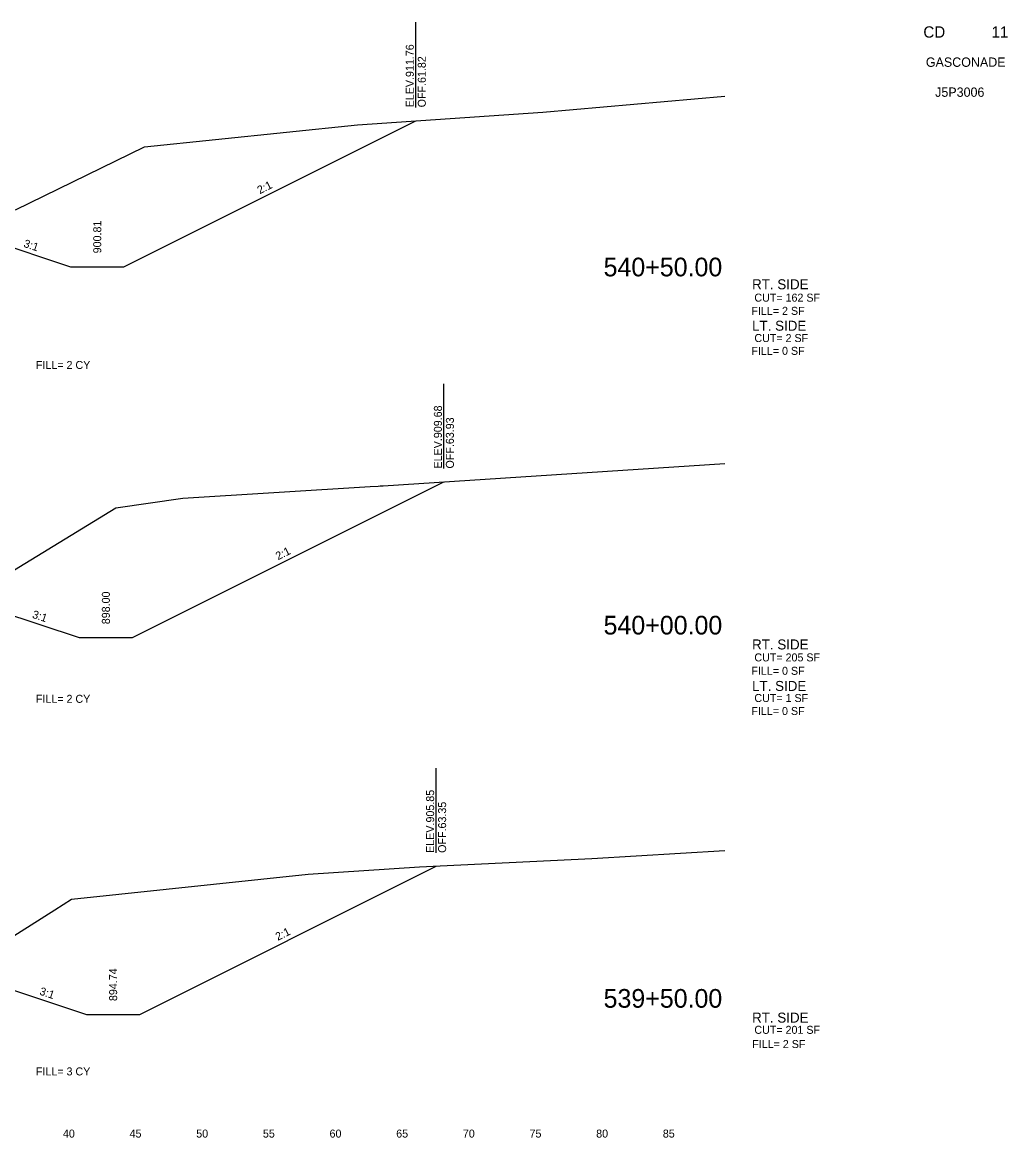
# Model space of a CAD drawing. Extents: x -4 to 359, y 0 to 1436.
# Drawn here: x 284.8 to 358.7, y 0.5 to 84.1 of the extents above; entities that cross this region are included whole.
import ezdxf

# ---------------------------------------------------------------- set-up
doc = ezdxf.new("R2010")
doc.units = 0
for name, color, linetype in [('Common-Title block info', 7, 'Continuous'), ('XS-Existing surface-ground', 7, 'Continuous'), ('XS-Proposed surface-ground', 7, 'Continuous'), ('XS-Text-ditch slope', 7, 'Continuous'), ('XS-Text-earthwork labels', 7, 'Continuous'), ('XS-Text-offset label', 7, 'Continuous'), ('XS-Text-profile report', 7, 'Continuous'), ('XS-Text-tie elevation', 7, 'Continuous'), ('XS-Text-tie offset', 7, 'Continuous')]:
    doc.layers.add(name, color=color, linetype=linetype)

msp = doc.modelspace()

# ---------------------------------------------------------------- linework, layer by layer
at = {"layer": 'XS-Existing surface-ground'}
for p, q in [((323.848, 77.412), (337.5, 78.606)), ((309.95, 76.461), (323.848, 77.412)), ((293.97, 74.809), (309.95, 76.461)), ((284.298, 70.082), (293.97, 74.809)), ((311.878, 49.381), (337.5, 51.043)), ((310.895, 49.334), (311.501, 49.361)), ((311.501, 49.361), (311.661, 49.369)), ((311.661, 49.369), (311.878, 49.381)), ((296.854, 48.45), (310.895, 49.334)), ((283.766, 42.803), (291.825, 47.733)), ((291.825, 47.733), (296.854, 48.45)), ((327.52, 21.421), (337.5, 22.029)), ((314.61, 20.792), (327.52, 21.421)), ((288.503, 18.369), (306.248, 20.266)), ((306.248, 20.266), (314.61, 20.792)), ((275.635, 10.244), (287.236, 17.592)), ((287.236, 17.592), (288.503, 18.369))]:
    msp.add_line(p, q, dxfattribs=at)
at = {"layer": 'XS-Proposed surface-ground'}
for points in [[(282.427, 67.793), (288.427, 65.813), (292.427, 65.813), (314.321, 76.76)], [(283.073, 39.978), (289.073, 37.998), (293.073, 37.998), (316.429, 49.676)], [(283.619, 11.718), (289.619, 9.738), (293.619, 9.738), (315.846, 20.852)]]:
    msp.add_lwpolyline(points, dxfattribs=at)
at = {"layer": 'XS-Text-tie offset'}
for p, q in [((314.321, 77.76), (314.321, 84.139)), ((316.429, 50.676), (316.429, 57.026)), ((315.846, 21.852), (315.846, 28.204))]:
    msp.add_line(p, q, dxfattribs=at)

# ---------------------------------------------------------------- texts
at = {"layer": 'Common-Title block info'}
for s, height, p in [('CD', 0.85, (352.395, 82.988)), ('11', 0.85, (357.512, 82.988)), ('GASCONADE', 0.7, (352.581, 80.801)), ('J5P3006', 0.7, (353.279, 78.551))]:
    msp.add_text(s, height=height, dxfattribs=at).set_placement(p)
at = {"layer": 'XS-Text-ditch slope'}
for s, rotation, p in [('2:1', 26.56505, (302.614, 71.242)), ('3:1', 341.73711, (284.856, 67.308)), ('2:1', 26.56505, (303.99, 43.792)), ('3:1', 341.73711, (285.502, 39.492)), ('2:1', 26.56505, (303.972, 15.251)), ('3:1', 341.73711, (286.048, 11.233))]:
    msp.add_text(s, height=0.6, rotation=rotation, dxfattribs=at).set_placement(p)
at = {"layer": 'XS-Text-earthwork labels'}
for s, height, p in [('RT. SIDE', 0.75, (339.547, 64.118)), (' CUT= 162 SF           ', 0.6, (339.495, 63.19)), ('FILL= 2 SF           ', 0.6, (339.495, 62.2)), ('LT. SIDE', 0.75, (339.547, 61.009)), (' CUT= 2 SF           ', 0.6, (339.495, 60.161)), ('FILL= 0 SF           ', 0.6, (339.495, 59.201)), ('FILL= 2 CY           ', 0.6, (285.826, 58.142)), ('RT. SIDE', 0.75, (339.547, 37.107)), (' CUT= 205 SF           ', 0.6, (339.495, 36.21)), ('FILL= 0 SF           ', 0.6, (339.495, 35.205)), ('LT. SIDE', 0.75, (339.547, 33.995)), ('FILL= 2 CY           ', 0.6, (285.826, 33.104)), (' CUT= 1 SF           ', 0.6, (339.495, 33.165)), ('FILL= 0 SF           ', 0.6, (339.495, 32.19)), ('RT. SIDE', 0.75, (339.547, 9.122)), (' CUT= 201 SF           ', 0.6, (339.495, 8.281)), ('FILL= 2 SF           ', 0.6, (339.556, 7.215)), ('FILL= 3 CY           ', 0.6, (285.826, 5.161))]:
    msp.add_text(s, height=height, dxfattribs=at).set_placement(p)
at = {"layer": 'XS-Text-offset label'}
for s, height, p in [('           540+50.00           ', 1.4, (322.687, 65.087)), ('           540+00.00           ', 1.4, (322.687, 38.229)), ('           539+50.00           ', 1.4, (322.687, 10.239)), ('           40           ', 0.6, (285.4, 0.5)), ('           45           ', 0.6, (290.4, 0.5)), ('           50           ', 0.6, (295.4, 0.5)), ('           55           ', 0.6, (300.4, 0.5)), ('           60           ', 0.6, (305.4, 0.5)), ('           65           ', 0.6, (310.4, 0.5)), ('           70           ', 0.6, (315.4, 0.5)), ('           75           ', 0.6, (320.4, 0.5)), ('           80           ', 0.6, (325.4, 0.5)), ('           85           ', 0.6, (330.4, 0.5))]:
    msp.add_text(s, height=height, dxfattribs=at).set_placement(p)
at = {"layer": 'XS-Text-profile report'}
for s, p in [('Dtch_Bkslp_1_T', (314.31, 76.76)), ('Rt_Agg_Layer_1_B13', (286.194, 66.545)), ('Dtch_Frslp_1_B', (288.416, 65.813)), ('Dtch_Bkslp_1_B', (292.416, 65.813)), ('Dtch_Bkslp_1_T', (316.418, 49.676)), ('Rt_Agg_Layer_1_B13', (286.815, 38.737)), ('Dtch_Frslp_1_B', (289.061, 37.997)), ('Dtch_Bkslp_1_B', (293.061, 37.997)), ('Dtch_Bkslp_1_T', (315.835, 20.851)), ('Rt_Agg_Layer_1_B13', (287.417, 10.459)), ('Dtch_Frslp_1_B', (289.607, 9.738)), ('Dtch_Bkslp_1_B', (293.607, 9.738))]:
    msp.add_text(s, height=0.00167, dxfattribs=at).set_placement(p)
at = {"layer": 'XS-Text-tie elevation'}
for s, p in [('ELEV.911.76', (314.171, 77.76)), ('OFF.61.82', (315.071, 77.76)), ('900.81', (290.727, 66.813)), ('ELEV.909.68', (316.279, 50.676)), ('OFF.63.93', (317.179, 50.676)), ('898.00', (291.373, 38.998)), ('ELEV.905.85', (315.696, 21.852)), ('OFF.63.35', (316.596, 21.852)), ('894.74', (291.919, 10.738))]:
    msp.add_text(s, height=0.6, rotation=90, dxfattribs=at).set_placement(p)

doc.saveas('drawing.dxf')
